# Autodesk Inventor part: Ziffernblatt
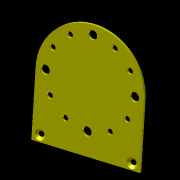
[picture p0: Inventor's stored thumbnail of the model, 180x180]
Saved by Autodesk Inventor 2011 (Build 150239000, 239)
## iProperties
Created: 2012-06
Part Number: Ziffernblatt
Document SubType Name: Modeling
Designer: M.Schulte
Density: 1 g/cm^3
Author: M.Schulte
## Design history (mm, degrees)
sketch "Skizze1" dims "d8" = 66
  geometry: L1 (-40, 0)-(40, 0); L2 (40, 0)-(40, 50); L3 (-40, 50)-(-40, 0); L4 (-40, 50)-(40, 50); L5 (0, -18)-(0, 108) reference; A1 r 40 centre (0, 50) between (40, 50) and (-40, 50); 17 further points
  constraints: 8 end point, 3 vertical alignment, 2 perpendicular, 2 point on circle, 2 tangent, 1 centre point, 1 coincident, 1 horizontal, 1 midpoint, 1 parallel, 1 symmetric about line, 15 other
  dimensions: "d0" = 80 distance of L1.start L1.end; "d2" = 40 radius of A1 (derived); "d6" = 50 distance of L1.end L2.end; "d7" = 50 distance of A1.centre point (0, 0); "d11" = 360 deg dimension on A1.centre point (0, 83) (derived); "d17" = 68 distance of point (34, 5) point (-34, 5); "d18" = 5 vertical distance of L1.start point (-34, 5)
extrude "Extrusion1" new body sketch "Skizze1" distance "d19" = 2; taper "d20" = 0 deg
hole "Hole1" sketch "Skizze1" diameter "d21" = 4; stored, may be unused: countersink angle "d25" = 90 deg, drill point angle "d27" = 118 deg; dims "d22" = 6, "d23" = 8, "d24" = 2, "d26" = 8
hole "Hole2" sketch "Skizze1" diameter "d28" = 6.8; stored, may be unused: countersink angle "d32" = 90 deg, drill point angle "d34" = 118 deg; dims "d29" = 6, "d30" = 8, "d31" = 2, "d33" = 8
hole "Hole3" sketch "Skizze1" diameter "d35" = 4.5; stored, may be unused: countersink angle "d39" = 90 deg, drill point angle "d41" = 118 deg; dims "d36" = 6, "d37" = 8, "d38" = 2, "d40" = 8
node "Volumenkörper1"
